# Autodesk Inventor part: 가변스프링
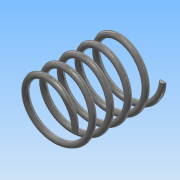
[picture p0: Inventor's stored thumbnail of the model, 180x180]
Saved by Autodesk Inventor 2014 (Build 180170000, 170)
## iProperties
Created: 2017-09
Part Number: 가변스프링
Material: 스테인레스 스틸
Document SubType Name: Modeling
Designer: user
Density: 8.08 g/cm^3
Appearance: 반연마
Mass: 7.86343 g
Surface Area: 19.7268 cm^2
Volume: 0.973196 cm^3
Author: user
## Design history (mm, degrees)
sketch "스케치1"
  geometry: L1 (0, 0)-(10, 0); L2 (10, 0)-(10, 30.5); L3 (10, 30.5)-(0, 30.5); L4 (0, 30.5)-(0, 0); C1 r 1 at (10, 0)
  constraints: 8 end point, 2 parallel, 1 centre point, 1 coincident, 1 horizontal, 1 perpendicular
  dimensions: "d0" = 20 diameter of L2 L4; "d1" = 2 diameter of C1; "d2" = 30.5 distance of L3.end L1.start (derived)
feature "코일1" sketch "스케치1" pitch "d3" = 10; turns "d5" = 5; dims "d4" = 30.5 (= d2), "d6" = 0, angle "d7" = 90 deg, angle "d8" = 90 deg, "d9" = 0, "d10" = 0
sketch "스케치2"
  geometry: L1 (0, 12.5)-(30.5, 12.5); L2 (30.5, 12.5)-(30.5, -12.5); L3 (30.5, -12.5)-(0, -12.5); L4 (0, -12.5)-(0, 12.5); 4 further points
  constraints: 8 end point, 2 coincident, 2 midpoint, 2 parallel, 1 horizontal, 1 perpendicular
  dimensions: "d11" = 25 distance between parallel lines of L3 L1
extrude "돌출1" sketch "스케치2" stored distance "d12" = 0; taper "d13" = 0 deg
node "솔리드1"
